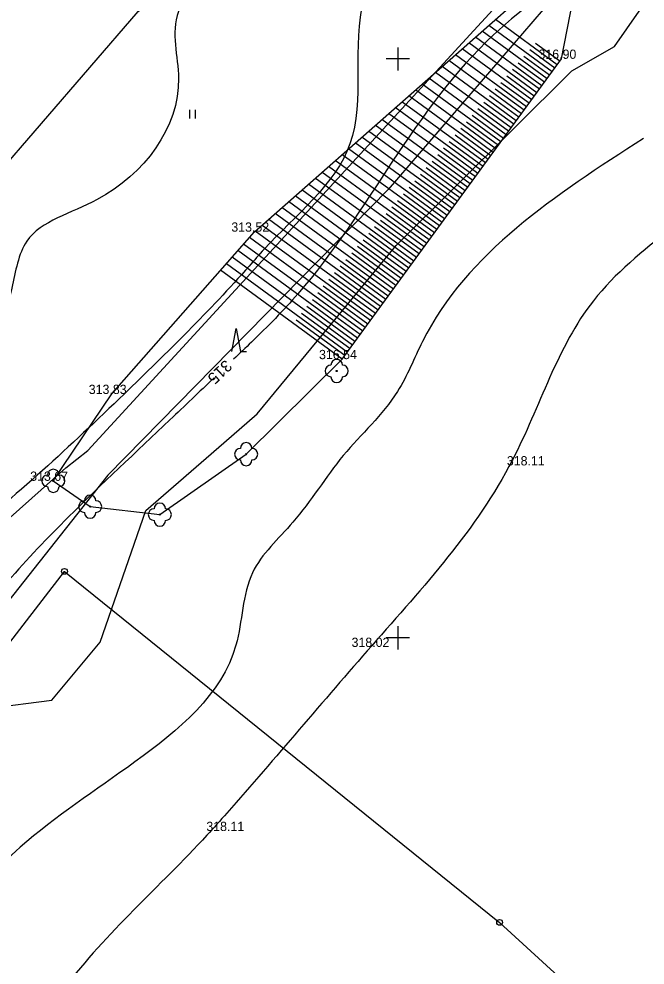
# Model space of a CAD drawing. Extents: x -504375 to -503125, y -1118000 to -1116474.
# Drawn here: x -503282.7 to -503228.6, y -1116678.3 to -1116596.5 of the extents above; entities that cross this region are included whole.
import ezdxf

# ---------------------------------------------------------------- set-up
doc = ezdxf.new("R2010")
doc.units = 0
for name, color, linetype in [('Druhy povrchů', 7, 'Continuous'), ('Podkladové mapy', 7, 'Continuous'), ('Stromy a keře', 7, 'Continuous'), ('Vrstva 34', 7, 'Continuous'), ('Vrstva 48', 7, 'Continuous'), ('Výškopis', 7, 'Continuous'), ('Výšky bodů plotr', 7, 'Continuous')]:
    doc.layers.add(name, color=color, linetype=linetype)

msp = doc.modelspace()

# ---------------------------------------------------------------- linework, layer by layer
at = {"layer": 'Druhy povrchů'}
for p, q in [((-503267.988, -1116605.153), (-503267.988, -1116604.403)), ((-503267.488, -1116605.153), (-503267.488, -1116604.403))]:
    msp.add_line(p, q, dxfattribs=at)
for points in [[(-503585.68, -1116948.36), (-503569.03, -1116928.88), (-503555.79, -1116911.97), (-503526.22, -1116880.66), (-503498.19, -1116855.24), (-503492.29, -1116850.5), (-503465.52, -1116813.76), (-503435.92, -1116779.91), (-503416.58, -1116756.7), (-503397.18, -1116739.15), (-503383.4, -1116725.23), (-503367.95, -1116706.66), (-503351.89, -1116693.92), (-503339.03, -1116678.06), (-503323.29, -1116660.89), (-503310.81, -1116645.12), (-503295.5, -1116628.53), (-503285, -1116610.41), (-503272.45, -1116595.9), (-503253.91, -1116580.94), (-503230.15, -1116566.71)], [(-503264.341, -1116625.269), (-503263.966, -1116623.269), (-503263.591, -1116625.269), (-503263.091, -1116625.269)]]:
    msp.add_lwpolyline(points, dxfattribs=at)
at = {"layer": 'Podkladové mapy'}
for p, q in [((-503276.78, -1116633.82), (-503233.98, -1116587.25)), ((-503233.96, -1116591.65), (-503250.83, -1116611.29)), ((-503250.83, -1116611.29), (-503275.06, -1116635.94)), ((-503278.7, -1116635.31), (-503276.78, -1116633.82)), ((-503275.06, -1116635.94), (-503288.25, -1116652.61)), ((-503283.77, -1116639.85), (-503278.7, -1116635.31)), ((-503293.3, -1116663.09), (-503278.81, -1116644.26)), ((-503278.81, -1116644.26), (-503241.21, -1116674.58)), ((-503241.21, -1116674.58), (-503210.25, -1116702.85))]:
    msp.add_line(p, q, dxfattribs=at)
for centre, radius in [((-503278.81, -1116644.26), 0.25), ((-503278.81, -1116644.26), 0.005), ((-503241.21, -1116674.58), 0.25), ((-503241.21, -1116674.58), 0.005)]:
    msp.add_circle(centre, radius, dxfattribs=at)
at = {"layer": 'Stromy a keře'}
for centre in [(-503255.282, -1116626.952), (-503263.11, -1116634.14), (-503279.77, -1116636.44), (-503276.59, -1116638.67), (-503270.57, -1116639.36)]:
    msp.add_circle(centre, 0.05, dxfattribs=at)
for centre, start, end in [((-503255.282, -1116626.452), 0, 180), ((-503255.782, -1116626.952), 90, 270), ((-503254.782, -1116626.952), 270, 90), ((-503255.282, -1116627.452), 180, 0), ((-503263.11, -1116633.64), 0, 180), ((-503263.61, -1116634.14), 90, 270), ((-503262.61, -1116634.14), 270, 90), ((-503263.11, -1116634.64), 180, 0), ((-503280.27, -1116636.44), 90, 270), ((-503279.77, -1116635.94), 0, 180), ((-503279.27, -1116636.44), 270, 90), ((-503279.77, -1116636.94), 180, 0), ((-503277.09, -1116638.67), 90, 270), ((-503276.59, -1116638.17), 0, 180), ((-503276.09, -1116638.67), 270, 90), ((-503270.57, -1116638.86), 0, 180), ((-503276.59, -1116639.17), 180, 0), ((-503271.07, -1116639.36), 90, 270), ((-503270.07, -1116639.36), 270, 90), ((-503270.57, -1116639.86), 180, 0)]:
    msp.add_arc(centre, 0.5, start, end, dxfattribs=at)
at = {"layer": 'Vrstva 34'}
for p, q in [((-503250, -1116599), (-503250, -1116601)), ((-503249, -1116600), (-503251, -1116600)), ((-503250, -1116649), (-503250, -1116651)), ((-503249, -1116650), (-503251, -1116650))]:
    msp.add_line(p, q, dxfattribs=at)
at = {"layer": 'Vrstva 48'}
msp.add_lwpolyline([(-503300.434, -1116681.166), (-503296.556, -1116668.103), (-503294.8, -1116667.049), (-503286.048, -1116656.931), (-503285.304, -1116656.071), (-503279.91, -1116655.384), (-503275.719, -1116650.391), (-503271.777, -1116639.009), (-503265.04, -1116633.168), (-503262.143, -1116630.656), (-503250.15, -1116616.106), (-503234.98, -1116601.014), (-503231.273, -1116598.925), (-503211.098, -1116569.991), (-503210.256, -1116567.168)], dxfattribs=at)
for points in [[(-503272.713, -1116521.984), (-503284.552, -1116530.049), (-503297.613, -1116538.288), (-503309.659, -1116545.506), (-503317.719, -1116548.279), (-503326.116, -1116552.563), (-503330.483, -1116554.327), (-503334.009, -1116555.839), (-503347.343, -1116563.628), (-503356.881, -1116570.175), (-503363.037, -1116574.013), (-503376.976, -1116580.659), (-503385.521, -1116583.565), (-503391.321, -1116585.975), (-503395.157, -1116587.671), (-503409.879, -1116592.332), (-503411.663, -1116592.332), (-503418.533, -1116597.758), (-503431.06, -1116606.789)], [(-503465.065, -1116647.979), (-503454.005, -1116643.254), (-503444.995, -1116644.684), (-503441.273, -1116642.635), (-503427.473, -1116633.37), (-503425.422, -1116628.769), (-503418.525, -1116619.631), (-503414.99, -1116617.273), (-503410.82, -1116614.036), (-503399.7, -1116608.038), (-503368.713, -1116598.755), (-503365.041, -1116596.617), (-503349.145, -1116588.639), (-503333.919, -1116577.69), (-503329.925, -1116576.242), (-503314.946, -1116570.728), (-503295.077, -1116561.657), (-503258.316, -1116548.433), (-503253.777, -1116542.843), (-503252.181, -1116542.843), (-503252.181, -1116548.832), (-503257.867, -1116556.916), (-503246.784, -1116552.513), (-503240.14, -1116547.809), (-503236.915, -1116548.947)], [(-503228.261, -1116563.145), (-503229.645, -1116567.016), (-503233.265, -1116571.228), (-503245.688, -1116584.541), (-503247.935, -1116586.867), (-503252.973, -1116594.854), (-503254.135, -1116607.338), (-503261.55, -1116616.428), (-503262.857, -1116617.898), (-503273.652, -1116628.941), (-503288.12, -1116641.769), (-503294.834, -1116647.413), (-503299.542, -1116653.756), (-503302.433, -1116657.068), (-503311.897, -1116663.915), (-503313.227, -1116667.667), (-503316.736, -1116674.505), (-503325.627, -1116690.3), (-503328.511, -1116695.009), (-503335.94, -1116707.278), (-503351.034, -1116723.382), (-503365.126, -1116737.245), (-503372.674, -1116748.782), (-503373.925, -1116753.16), (-503378.551, -1116760.666), (-503382.552, -1116767.547), (-503390.579, -1116780.739), (-503398.79, -1116793.818), (-503400.908, -1116797.881), (-503402.495, -1116807.226), (-503404.198, -1116812.046), (-503412.471, -1116822.312), (-503418.387, -1116829.995), (-503420.024, -1116835.788), (-503425.814, -1116843.155), (-503430.336, -1116857.921), (-503433.683, -1116863.223), (-503434.674, -1116865.019), (-503440.926, -1116880.75), (-503445.259, -1116893.88)], [(-503481.504, -1116663.518), (-503468.547, -1116657.036), (-503463.489, -1116655.349), (-503455.413, -1116652.508), (-503447.337, -1116652.508), (-503443.352, -1116653.982), (-503430.298, -1116650.555), (-503416.187, -1116635.106), (-503410.685, -1116628.713), (-503402.504, -1116619.064), (-503381.737, -1116613.158), (-503370.807, -1116610.971), (-503361.189, -1116605.649), (-503353.61, -1116601.494), (-503341.223, -1116596.974), (-503328.544, -1116591.798), (-503324.172, -1116589.392), (-503302.385, -1116583.924), (-503293.932, -1116583.924), (-503286.266, -1116582.08), (-503284.637, -1116580.965), (-503272.933, -1116568.697), (-503269.17, -1116566.723), (-503271.089, -1116569.984), (-503281.636, -1116583.324), (-503281.636, -1116584.01), (-503265.516, -1116590.53), (-503268.945, -1116595.892), (-503268.945, -1116601.682), (-503275.976, -1116612.148), (-503282.064, -1116615.751), (-503283.352, -1116619.8), (-503288.876, -1116631.779), (-503303.377, -1116644.015), (-503307.12, -1116648.093), (-503316.743, -1116659.793), (-503321.087, -1116663.538), (-503326.965, -1116676.097), (-503331.52, -1116684.914), (-503334.134, -1116690.218), (-503342.049, -1116704.413), (-503355.564, -1116718.999), (-503373.009, -1116735.836), (-503382.317, -1116749.959), (-503386.693, -1116758.655), (-503400.779, -1116777.303), (-503409.619, -1116795.183), (-503415, -1116808.93), (-503418.611, -1116811.169), (-503424.106, -1116823.61), (-503426.69, -1116826.983), (-503429.797, -1116836.064), (-503433.946, -1116846.027), (-503439.043, -1116851.839), (-503444.852, -1116860.972), (-503445.916, -1116865.085), (-503449.799, -1116874.02), (-503458.366, -1116891.656), (-503466.054, -1116907.093), (-503467.087, -1116909.659), (-503470.52, -1116921.657)], [(-503220.996, -1116567.416), (-503217.756, -1116573.319), (-503221.427, -1116577.942), (-503233.269, -1116590.886), (-503241.732, -1116597.917), (-503258.62, -1116620.268), (-503262.643, -1116624.456), (-503264.199, -1116625.94)], [(-503228.777, -1116606.86), (-503247.87, -1116624.41), (-503250.03, -1116628.733), (-503254.714, -1116634.261), (-503259.075, -1116640.018), (-503262.555, -1116644.382), (-503263.994, -1116650.649), (-503272.717, -1116660.722), (-503282.634, -1116668.097), (-503288.112, -1116673.922), (-503293.167, -1116682.582), (-503295.386, -1116689.523), (-503299.495, -1116695.666), (-503301.478, -1116696.972), (-503309.455, -1116706.405), (-503311.196, -1116710.807), (-503320.257, -1116722.456), (-503324.189, -1116726.952), (-503334.409, -1116738.528), (-503337.358, -1116741.127), (-503347.86, -1116754.564), (-503355.556, -1116772.228), (-503356.178, -1116773.87), (-503361.611, -1116782.873), (-503368.324, -1116799.361)], [(-503226.376, -1116614.632), (-503233.107, -1116620.885), (-503240.101, -1116634.653), (-503252.255, -1116650.684), (-503264.774, -1116665.135), (-503266.507, -1116667.062), (-503278.833, -1116680.261), (-503283.648, -1116688.161), (-503287.693, -1116698.856)], [(-503265.883, -1116627.544), (-503269.693, -1116631.175), (-503278.458, -1116639.563), (-503288.462, -1116651.097), (-503292.309, -1116656.624), (-503295.894, -1116660.249), (-503304.85, -1116666.159), (-503306.392, -1116672.714), (-503319.808, -1116694.279), (-503329.527, -1116709.34), (-503332.099, -1116712.391), (-503343.962, -1116725.645), (-503346.759, -1116728.532), (-503357.339, -1116738.854), (-503363.022, -1116747.777), (-503365.151, -1116754.165), (-503367.044, -1116758.186), (-503370.891, -1116765.184), (-503373.427, -1116769.471), (-503379.022, -1116778.131), (-503381.668, -1116782.909)]]:
    msp.add_spline(points, degree=3, dxfattribs=at)
at = {"layer": 'Výškopis'}
for p, q in [((-503236.222, -1116600.499), (-503241.57, -1116596.59)), ((-503236.665, -1116601.104), (-503242.147, -1116597.097)), ((-503237.55, -1116602.315), (-503243.3, -1116598.113)), ((-503237.107, -1116601.71), (-503242.723, -1116597.605)), ((-503238.435, -1116603.526), (-503244.453, -1116599.128)), ((-503237.992, -1116602.921), (-503243.876, -1116598.62)), ((-503236.001, -1116600.196), (-503238.113, -1116598.652)), ((-503238.877, -1116604.132), (-503245.03, -1116599.635)), ((-503236.886, -1116601.407), (-503239.106, -1116599.785)), ((-503236.443, -1116600.802), (-503238.609, -1116599.218)), ((-503239.763, -1116605.343), (-503246.183, -1116600.65)), ((-503239.32, -1116604.737), (-503245.606, -1116600.143)), ((-503237.328, -1116602.013), (-503239.602, -1116600.351)), ((-503240.205, -1116605.948), (-503246.759, -1116601.158)), ((-503238.214, -1116603.224), (-503240.594, -1116601.484)), ((-503237.771, -1116602.618), (-503240.098, -1116600.918)), ((-503241.09, -1116607.159), (-503247.912, -1116602.173)), ((-503240.648, -1116606.554), (-503247.336, -1116601.666)), ((-503238.656, -1116603.829), (-503241.09, -1116602.05)), ((-503241.975, -1116608.37), (-503249.065, -1116603.188)), ((-503241.533, -1116607.765), (-503248.489, -1116602.681)), ((-503239.541, -1116605.04), (-503242.083, -1116603.183)), ((-503239.099, -1116604.435), (-503241.586, -1116602.616)), ((-503242.418, -1116608.976), (-503249.642, -1116603.696)), ((-503239.984, -1116605.646), (-503242.579, -1116603.749)), ((-503243.303, -1116610.187), (-503250.795, -1116604.711)), ((-503242.861, -1116609.581), (-503250.218, -1116604.204)), ((-503240.869, -1116606.857), (-503243.571, -1116604.882)), ((-503240.426, -1116606.251), (-503243.075, -1116604.316)), ((-503244.188, -1116611.398), (-503251.948, -1116605.726)), ((-503243.746, -1116610.792), (-503251.371, -1116605.219)), ((-503241.312, -1116607.462), (-503244.067, -1116605.448)), ((-503244.631, -1116612.003), (-503252.524, -1116606.234)), ((-503241.754, -1116608.068), (-503244.563, -1116606.014)), ((-503245.516, -1116613.214), (-503253.677, -1116607.249)), ((-503245.073, -1116612.609), (-503253.101, -1116606.742)), ((-503242.639, -1116609.279), (-503245.555, -1116607.147)), ((-503242.197, -1116608.673), (-503245.06, -1116606.581)), ((-503245.959, -1116613.82), (-503254.254, -1116607.757)), ((-503243.082, -1116609.884), (-503246.052, -1116607.714)), ((-503246.844, -1116615.031), (-503255.407, -1116608.772)), ((-503246.401, -1116614.425), (-503254.83, -1116608.264)), ((-503243.967, -1116611.095), (-503247.044, -1116608.846)), ((-503243.524, -1116610.49), (-503246.548, -1116608.28)), ((-503247.729, -1116616.242), (-503256.56, -1116609.787)), ((-503247.286, -1116615.636), (-503255.983, -1116609.279)), ((-503244.41, -1116611.701), (-503247.54, -1116609.412)), ((-503248.171, -1116616.847), (-503257.137, -1116610.295)), ((-503245.295, -1116612.912), (-503248.532, -1116610.545)), ((-503244.852, -1116612.306), (-503248.036, -1116609.979)), ((-503249.057, -1116618.058), (-503258.29, -1116611.31)), ((-503248.614, -1116617.453), (-503257.713, -1116610.802)), ((-503245.737, -1116613.517), (-503249.029, -1116611.112)), ((-503249.499, -1116618.664), (-503258.866, -1116611.817)), ((-503246.622, -1116614.728), (-503250.021, -1116612.244)), ((-503246.18, -1116614.123), (-503249.525, -1116611.678)), ((-503250.384, -1116619.875), (-503260.019, -1116612.833)), ((-503249.942, -1116619.269), (-503259.443, -1116612.325)), ((-503247.065, -1116615.334), (-503250.517, -1116612.81)), ((-503251.269, -1116621.086), (-503261.172, -1116613.848)), ((-503250.827, -1116620.48), (-503260.596, -1116613.34)), ((-503247.508, -1116615.939), (-503251.013, -1116613.377)), ((-503251.712, -1116621.691), (-503261.749, -1116614.355)), ((-503248.393, -1116617.15), (-503252.006, -1116614.51)), ((-503247.95, -1116616.545), (-503251.509, -1116613.943)), ((-503252.597, -1116622.902), (-503262.831, -1116615.422)), ((-503252.155, -1116622.297), (-503262.325, -1116614.863)), ((-503248.835, -1116617.756), (-503252.502, -1116615.076)), ((-503253.04, -1116623.508), (-503263.328, -1116615.988)), ((-503249.72, -1116618.967), (-503253.494, -1116616.209)), ((-503249.278, -1116618.361), (-503252.998, -1116615.642)), ((-503253.925, -1116624.719), (-503264.323, -1116617.119)), ((-503253.482, -1116624.113), (-503263.825, -1116616.553)), ((-503250.163, -1116619.572), (-503253.99, -1116616.775)), ((-503254.367, -1116625.324), (-503264.82, -1116617.685)), ((-503251.048, -1116620.783), (-503254.983, -1116617.908)), ((-503250.606, -1116620.178), (-503254.486, -1116617.341)), ((-503254.81, -1116625.93), (-503265.317, -1116618.25)), ((-503251.491, -1116621.389), (-503255.479, -1116618.474)), ((-503252.376, -1116622.6), (-503256.459, -1116619.616)), ((-503251.933, -1116621.994), (-503255.975, -1116619.04)), ((-503252.818, -1116623.205), (-503256.923, -1116620.205)), ((-503253.261, -1116623.811), (-503257.387, -1116620.795)), ((-503254.146, -1116625.022), (-503258.316, -1116621.974)), ((-503253.704, -1116624.416), (-503257.852, -1116621.384)), ((-503254.589, -1116625.627), (-503258.781, -1116622.564))]:
    msp.add_line(p, q, dxfattribs=at)
for points in [[(-503279.77, -1116636.44), (-503274.71, -1116628.94), (-503262.39, -1116614.92), (-503233.87, -1116589.81)], [(-503235.85, -1116599.99), (-503233.87, -1116589.81)], [(-503254.81, -1116625.93), (-503235.85, -1116599.99)], [(-503279.77, -1116636.44), (-503276.59, -1116638.67), (-503270.57, -1116639.36), (-503263.11, -1116634.14), (-503254.81, -1116625.93)]]:
    msp.add_lwpolyline(points, dxfattribs=at)

# ---------------------------------------------------------------- texts
at = {"layer": 'Vrstva 48'}
msp.add_text('315', height=1, rotation=223.60962, dxfattribs=at).set_placement((-503264.907, -1116625.924))
at = {"layer": 'Výšky bodů plotr'}
for s, p in [('316.90 ', (-503237.85, -1116599.99)), ('313.52 ', (-503264.39, -1116614.92)), ('316.54 ', (-503256.81, -1116625.93)), ('313.83 ', (-503276.71, -1116628.94)), ('318.11 ', (-503240.58, -1116635.11)), ('313.67 ', (-503281.77, -1116636.44)), ('318.02 ', (-503254, -1116650.79)), ('318.11 ', (-503266.55, -1116666.69))]:
    msp.add_text(s, height=0.8, dxfattribs=at).set_placement(p)

doc.saveas('drawing.dxf')
